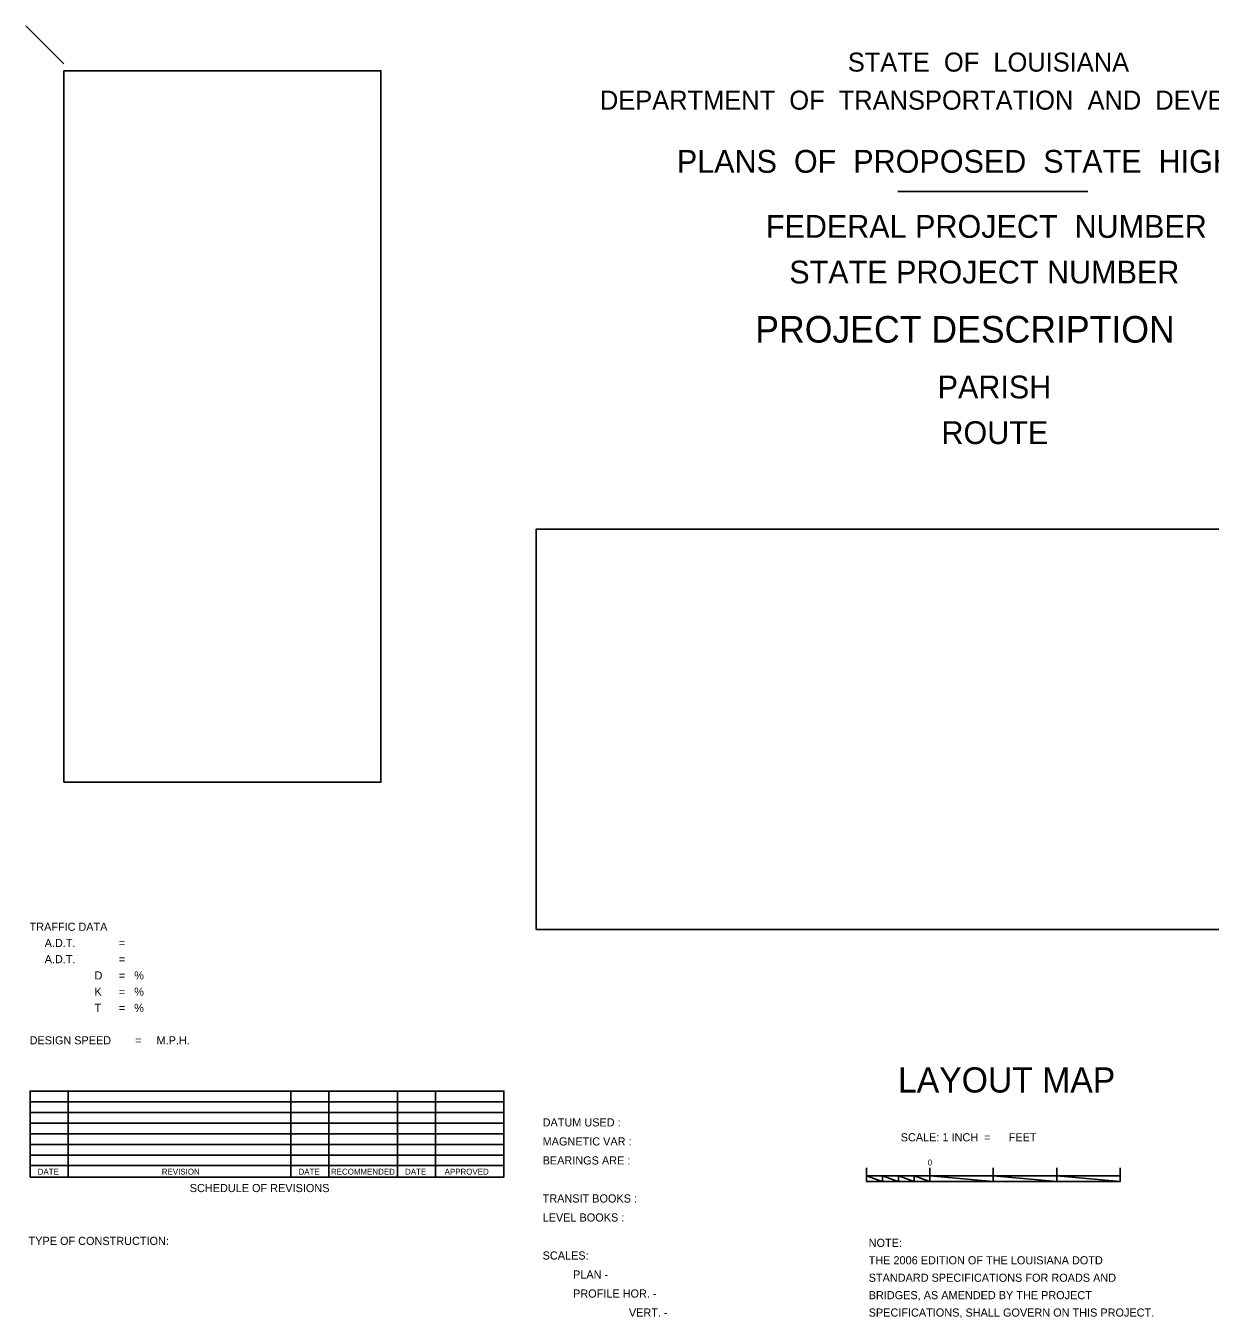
# Model space of a CAD drawing. Extents: x 0.23 to 2.82, y 0.04 to 1.79.
# Drawn here: x 0.233 to 1.79, y 0.093 to 1.792 of the extents above; entities that cross this region are included whole.
import ezdxf

# ---------------------------------------------------------------- set-up
doc = ezdxf.new("R2010")
doc.units = 0
for name, color, linetype in [('Annotation', 7, 'Continuous'), ('Layout Map Info', 7, 'Continuous'), ('Standard Info', 7, 'Continuous')]:
    doc.layers.add(name, color=color, linetype=linetype)

msp = doc.modelspace()

# ---------------------------------------------------------------- linework, layer by layer
at = {"layer": 'Annotation'}
msp.add_lwpolyline([(0.2833, 0.7972), (0.7, 0.7972), (0.7, 1.7327), (0.2833, 1.7327)], close=True, dxfattribs=at)
at = {"layer": 'Layout Map Info'}
msp.add_lwpolyline([(0.9038, 0.6035), (2.1045, 0.6035), (2.1045, 1.1298), (0.9038, 1.1298)], close=True, dxfattribs=at)
at = {"layer": 'Standard Info'}
for p, q in [((0.2333, 1.7917), (0.2833, 1.7417)), ((1.3792, 1.5741), (1.6292, 1.5741)), ((0.2888, 0.2782), (0.2888, 0.3912)), ((0.5816, 0.2782), (0.5816, 0.3912)), ((0.5816, 0.3174), (0.5816, 0.3912)), ((0.6316, 0.2782), (0.6316, 0.3912)), ((0.7216, 0.2782), (0.7216, 0.3912)), ((0.7716, 0.2782), (0.7716, 0.3912)), ((0.2388, 0.3772), (0.5816, 0.3772)), ((0.5816, 0.3772), (0.8616, 0.3772)), ((0.2388, 0.3632), (0.5816, 0.3632)), ((0.5816, 0.3632), (0.8616, 0.3632)), ((0.2388, 0.3493), (0.5816, 0.3493)), ((0.5816, 0.3493), (0.8616, 0.3493)), ((0.2388, 0.3352), (0.5816, 0.3352)), ((0.5816, 0.3352), (0.8616, 0.3352)), ((0.2388, 0.3212), (0.5816, 0.3212)), ((0.2388, 0.3072), (0.5816, 0.3072)), ((0.5816, 0.3212), (0.8616, 0.3212)), ((0.5816, 0.2782), (0.5816, 0.3174)), ((0.5816, 0.3072), (0.8616, 0.3072)), ((0.2388, 0.2933), (0.5816, 0.2933)), ((0.5816, 0.2933), (0.8616, 0.2933)), ((1.3381, 0.2723), (1.3381, 0.2906)), ((1.4215, 0.2723), (1.4215, 0.2906)), ((1.5048, 0.2723), (1.5048, 0.2906)), ((1.5881, 0.2723), (1.5881, 0.2906)), ((1.6715, 0.2906), (1.6715, 0.2723)), ((1.3381, 0.2801), (1.6715, 0.2801)), ((1.3381, 0.2723), (1.6715, 0.2723))]:
    msp.add_line(p, q, dxfattribs=at)
for points in [[(0.2388, 0.2782), (0.8616, 0.2782), (0.8616, 0.3912), (0.2388, 0.3912)], [(1.3381, 0.2723), (1.3381, 0.2801), (1.3589, 0.2723)], [(1.359, 0.2723), (1.359, 0.2801), (1.3798, 0.2723)], [(1.38, 0.2723), (1.38, 0.2801), (1.4007, 0.2723)], [(1.4006, 0.2723), (1.4006, 0.2801), (1.4215, 0.2723)], [(1.4215, 0.2723), (1.4215, 0.2801), (1.5048, 0.2723)], [(1.5048, 0.2723), (1.5048, 0.2801), (1.5881, 0.2723)], [(1.5881, 0.2723), (1.5881, 0.2801), (1.6715, 0.2723)]]:
    msp.add_lwpolyline(points, close=True, dxfattribs=at)

# ---------------------------------------------------------------- texts
for s, height, p in [('STATE  OF  LOUISIANA', 0.025, (1.3136, 1.7315)), ('DEPARTMENT  OF  TRANSPORTATION  AND  DEVELOPMENT', 0.025, (0.9878, 1.6815)), ('PLANS  OF  PROPOSED  STATE  HIGHWAY', 0.03, (1.0889, 1.5985)), ('          FEDERAL PROJECT  NUMBER         ', 0.03, (1.0944, 1.513)), ('         STATE PROJECT NUMBER         ', 0.03, (1.1363, 1.453)), ('           PROJECT DESCRIPTION          ', 0.035, (1.0489, 1.3752)), ('         PARISH        ', 0.03, (1.3313, 1.3019)), ('         ROUTE        ', 0.03, (1.3363, 1.2419)), ('TRAFFIC DATA', 0.010667, (0.2383, 0.602)), ('     A.D.T.', 0.010667, (0.2383, 0.5807)), ('=        ', 0.01067, (0.3556, 0.5807)), ('     A.D.T.', 0.010667, (0.2383, 0.5594)), ('=        ', 0.01067, (0.3556, 0.5594)), ('D', 0.0107, (0.3236, 0.538)), ('=   %', 0.01067, (0.3556, 0.538)), ('K', 0.0107, (0.3236, 0.5167)), ('=   %', 0.01067, (0.3556, 0.5167)), ('T', 0.0107, (0.3236, 0.4954)), ('=   %', 0.01067, (0.3556, 0.4954)), ('DESIGN SPEED', 0.010667, (0.2383, 0.4527)), ('=     M.P.H.', 0.010667, (0.377, 0.4527)), ('LAYOUT MAP', 0.03313, (1.3795, 0.3894)), ('DATUM USED :                   ', 0.0107, (0.9125, 0.3448)), ('MAGNETIC VAR :                 ', 0.0107, (0.9125, 0.3198)), ('SCALE: 1 INCH  =      FEET', 0.0107, (1.3831, 0.3252)), ('DATE', 0.0078, (0.2489, 0.2814)), ('REVISION', 0.0078, (0.412, 0.2814)), ('DATE', 0.0078, (0.5917, 0.2814)), ('RECOMMENDED', 0.0078, (0.6343, 0.2814)), ('DATE', 0.0078, (0.7317, 0.2814)), ('APPROVED', 0.0078, (0.7837, 0.2814)), ('BEARINGS ARE :                 ', 0.0107, (0.9125, 0.2948)), ('0', 0.0078, (1.4186, 0.2935)), ('SCHEDULE OF REVISIONS', 0.0107, (0.4487, 0.2585)), ('TRANSIT BOOKS :                ', 0.0107, (0.9125, 0.2448)), ('LEVEL BOOKS :                  ', 0.0107, (0.9125, 0.2198)), ('TYPE OF CONSTRUCTION:', 0.0107, (0.2369, 0.189)), ('NOTE:', 0.0107, (1.341, 0.1864)), ('SCALES:', 0.0107, (0.9125, 0.1698)), ('THE 2006 EDITION OF THE LOUISIANA DOTD', 0.0107, (1.341, 0.1635)), ('PLAN -                         ', 0.0107, (0.9525, 0.1448)), ('STANDARD SPECIFICATIONS FOR ROADS AND', 0.0107, (1.341, 0.1406)), ('PROFILE HOR. -                ', 0.0107, (0.9525, 0.1198)), ('BRIDGES, AS AMENDED BY THE PROJECT', 0.0107, (1.341, 0.1177)), ('VERT. -                ', 0.0107, (1.0259, 0.0948)), ('SPECIFICATIONS, SHALL GOVERN ON THIS PROJECT.', 0.0107, (1.341, 0.0948))]:
    msp.add_text(s, height=height, dxfattribs=at).set_placement(p)

doc.saveas('drawing.dxf')
